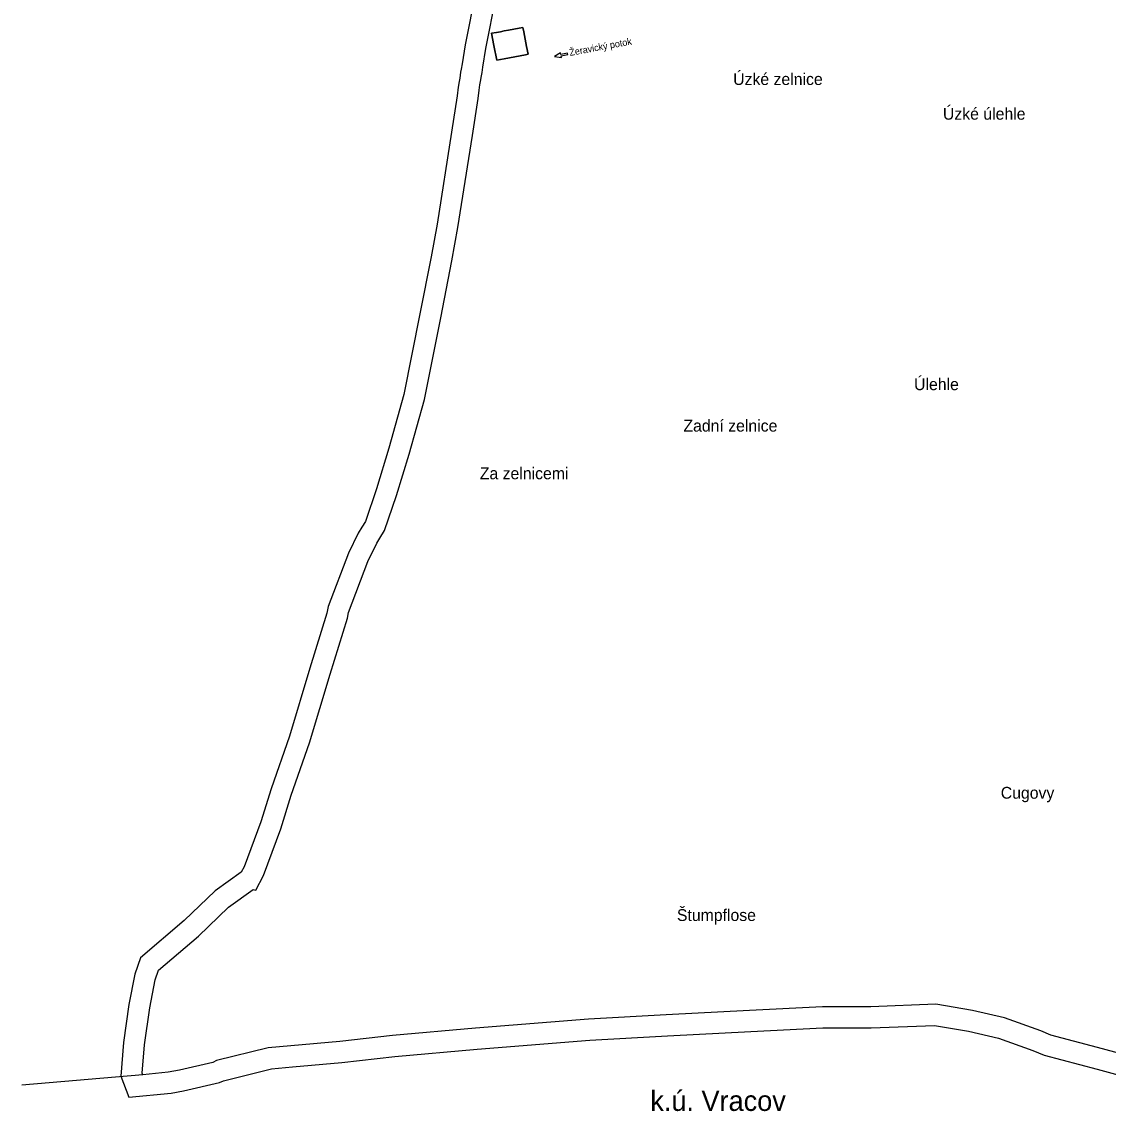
# Model space of a CAD drawing. Extents: x -555651 to -552898, y -1186794 to -1182535.
# Drawn here: x -555651 to -554364, y -1186786 to -1185494 of the extents above; entities that cross this region are included whole.
import ezdxf

# ---------------------------------------------------------------- set-up
doc = ezdxf.new("R2010")
doc.units = 0
for name, color, linetype in [('Level 2', 7, 'Continuous'), ('Level 3', 7, 'Continuous'), ('Level 30', 7, 'Continuous'), ('Level 32', 7, 'Continuous'), ('Level 57', 7, 'Continuous'), ('stav_OT', 7, 'Continuous'), ('ZASTAVENE_UZEMI', 7, 'Continuous')]:
    doc.layers.add(name, color=color, linetype=linetype)

msp = doc.modelspace()

# ---------------------------------------------------------------- linework, layer by layer
at = {"layer": 'Level 3'}
for p, q in [((-555012.854, -1185533.261), (-555013.267, -1185531.301)), ((-555005.023, -1185531.583), (-555012.854, -1185533.261)), ((-555012.513, -1185534.823), (-555004.692, -1185533.148)), ((-555012.095, -1185536.779), (-555012.513, -1185534.823)), ((-555004.692, -1185533.148), (-555005.023, -1185531.583))]:
    msp.add_line(p, q, dxfattribs=at)
for points in [[(-555013.267, -1185531.301), (-555020.506, -1185535.717)], [(-555020.506, -1185535.717), (-555012.095, -1185536.779)]]:
    msp.add_lwpolyline(points, dxfattribs=at)
at = {"layer": 'Level 30'}
for points in [[(-555113.633, -1185457.754), (-555126.215, -1185521.754), (-555129.927, -1185544.271), (-555130.948, -1185550.461), (-555131.577, -1185554.296), (-555132.73, -1185561.261), (-555133.36, -1185565.133), (-555134.498, -1185572.017), (-555135.598, -1185582.129), (-555142.388, -1185625.178), (-555159.376, -1185734.191), (-555166.618, -1185773.168), (-555179.758, -1185840.365), (-555198.817, -1185936.293), (-555216.478, -1185999.714), (-555231.301, -1186048.099), (-555244.387, -1186086.552), (-555248.487, -1186093.194), (-555252.857, -1186100.283), (-555264.519, -1186124.09), (-555288.498, -1186187.536), (-555289.998, -1186195.183), (-555310.113, -1186260.408), (-555334.437, -1186341.098), (-555356.203, -1186403.269), (-555368.444, -1186442.679), (-555388.188, -1186495.914), (-555391.439, -1186502.2), (-555422.576, -1186524.215), (-555459.116, -1186559.456), (-555511.009, -1186603.724), (-555517.63, -1186623.28), (-555524.573, -1186659.039), (-555530.99, -1186704.258)], [(-555506.13, -1186707.01), (-555499.91, -1186663.18), (-555493.41, -1186629.7), (-555489.54, -1186618.27), (-555442.31, -1186577.98), (-555406.59, -1186543.53), (-555377.44, -1186522.92), (-555374.35, -1186523.58), (-555365.28, -1186506.04), (-555344.77, -1186450.74), (-555332.46, -1186411.11), (-555310.66, -1186348.84), (-555286.2, -1186267.7), (-555265.72, -1186201.29), (-555264.37, -1186194.41), (-555241.55, -1186134.03), (-555230.94, -1186112.37), (-555227.21, -1186106.32), (-555221.63, -1186097.28), (-555207.51, -1186055.79), (-555192.48, -1186006.73), (-555174.48, -1185942.09), (-555155.23, -1185845.2), (-555142.06, -1185777.85), (-555134.73, -1185738.4), (-555117.69, -1185629.05), (-555110.81, -1185585.43), (-555109.72, -1185575.41), (-555108.69, -1185569.18), (-555108.06, -1185565.31), (-555106.91, -1185558.36), (-555106.28, -1185554.52), (-555105.26, -1185548.34), (-555101.61, -1185526.2), (-555089.38, -1185463.99)], [(-554318.68, -1186725.91), (-554371.15, -1186711.4), (-554432.23, -1186695.45), (-554444.35, -1186690.16), (-554487.24, -1186674.75), (-554525.06, -1186666.06), (-554568.51, -1186658.81), (-554645.82, -1186661.76), (-554703.03, -1186661.84), (-554789.24, -1186666.07), (-554887.97, -1186671.38), (-554980.05, -1186676.42), (-555114.15, -1186687.17), (-555212.22, -1186695.72), (-555274.79, -1186703.08), (-555332.83, -1186708.02)], [(-555330.71, -1186732.93), (-555272.269, -1186727.956), (-555209.673, -1186720.593), (-555112.065, -1186712.083), (-554978.368, -1186701.365), (-554886.616, -1186696.343), (-554787.956, -1186691.037), (-554702.4, -1186686.839), (-554645.326, -1186686.759), (-554570.107, -1186683.889), (-554529.921, -1186690.595), (-554494.291, -1186698.781), (-554453.587, -1186713.406), (-554440.438, -1186719.145), (-554377.64, -1186735.543), (-554325.272, -1186750.025)], [(-555530.99, -1186704.258), (-555534.153, -1186743.958), (-555524.481, -1186769.03), (-555474.566, -1186763.987), (-555459.837, -1186761.473), (-555417.205, -1186751.437), (-555412.5, -1186749.325), (-555355.454, -1186735.293), (-555330.71, -1186732.93)], [(-555332.83, -1186708.02), (-555359.65, -1186710.58), (-555420.67, -1186725.59), (-555425.26, -1186727.65), (-555464.81, -1186736.96), (-555477.93, -1186739.2), (-555508.02, -1186742.24), (-555508.78, -1186740.27), (-555506.13, -1186707.01)]]:
    msp.add_lwpolyline(points, dxfattribs=at)
at = {"layer": 'Level 32'}
msp.add_lwpolyline([(-555092.18, -1185522.55), (-555094.96, -1185508.08), (-555089.21, -1185507), (-555084.52, -1185506.13), (-555079.88, -1185505.26), (-555074.79, -1185504.31), (-555062.21, -1185501.96), (-555057.82, -1185501.14), (-555056.79, -1185506.46), (-555053.44, -1185523.9), (-555051.7, -1185532.91), (-555054.94, -1185533.53), (-555067.4, -1185535.93), (-555079.9, -1185538.34), (-555088.82, -1185540.06), (-555092.18, -1185522.55)], dxfattribs=at)
at = {"layer": 'Level 57'}
for points in [[(-555067.4, -1185535.93), (-555054.94, -1185533.53), (-555051.7, -1185532.91), (-555053.44, -1185523.9), (-555056.79, -1185506.46), (-555057.82, -1185501.14), (-555062.21, -1185501.96), (-555074.79, -1185504.31), (-555079.88, -1185505.26), (-555084.52, -1185506.13), (-555089.21, -1185507), (-555094.96, -1185508.08), (-555092.18, -1185522.55)], [(-555092.18, -1185522.55), (-555088.82, -1185540.06), (-555079.9, -1185538.34), (-555067.4, -1185535.93)]]:
    msp.add_lwpolyline(points, dxfattribs=at)
at = {"layer": 'stav_OT'}
for points in [[(-555506.13, -1186707.01), (-555499.91, -1186663.18), (-555493.41, -1186629.7), (-555489.54, -1186618.27), (-555442.31, -1186577.98), (-555406.59, -1186543.53), (-555377.44, -1186522.92), (-555374.35, -1186523.58), (-555365.28, -1186506.04), (-555344.77, -1186450.74), (-555332.46, -1186411.11), (-555310.66, -1186348.84), (-555286.2, -1186267.7), (-555265.72, -1186201.29), (-555264.37, -1186194.41), (-555241.55, -1186134.03), (-555230.94, -1186112.37), (-555227.21, -1186106.32), (-555221.63, -1186097.28), (-555207.51, -1186055.79), (-555192.48, -1186006.73), (-555174.48, -1185942.09), (-555155.23, -1185845.2), (-555142.06, -1185777.85), (-555134.73, -1185738.4), (-555117.69, -1185629.05), (-555110.81, -1185585.43), (-555109.72, -1185575.41), (-555108.69, -1185569.18), (-555108.06, -1185565.31), (-555106.91, -1185558.36), (-555106.28, -1185554.52), (-555105.26, -1185548.34), (-555101.61, -1185526.2), (-555089.38, -1185463.99)], [(-554318.68, -1186725.91), (-554371.15, -1186711.4), (-554432.23, -1186695.45), (-554444.35, -1186690.16), (-554487.24, -1186674.75), (-554525.06, -1186666.06), (-554568.51, -1186658.81), (-554645.82, -1186661.76), (-554703.03, -1186661.84), (-554789.24, -1186666.07), (-554887.97, -1186671.38), (-554980.05, -1186676.42), (-555114.15, -1186687.17), (-555212.22, -1186695.72), (-555274.79, -1186703.08), (-555332.83, -1186708.02)], [(-555332.83, -1186708.02), (-555359.65, -1186710.58), (-555420.67, -1186725.59), (-555425.26, -1186727.65), (-555464.81, -1186736.96), (-555477.93, -1186739.2), (-555508.02, -1186742.24), (-555508.78, -1186740.27), (-555506.13, -1186707.01)], [(-555508.02, -1186742.24), (-555651.457, -1186754.806)]]:
    msp.add_lwpolyline(points, dxfattribs=at)

# ---------------------------------------------------------------- texts
at = {"layer": 'Level 2'}
for s, p in [('Úzké zelnice', (-554808.775, -1185569.331)), ('Úzké úlehle', (-554560.255, -1185610.441)), ('Úlehle', (-554594.428, -1185930.971)), ('Zadní zelnice', (-554867.705, -1185980.101)), ('Za zelnicemi', (-555108.914, -1186036.566)), ('Cugovy', (-554491.756, -1186415.147)), ('Štumpflose', (-554875.401, -1186560.076))]:
    msp.add_text(s, height=14, dxfattribs=at).set_placement(p)
at = {"layer": 'Level 3'}
msp.add_text('Žeravický potok', height=8, rotation=10.468278, dxfattribs=at).set_placement((-555002.042, -1185534.921))
at = {"layer": 'ZASTAVENE_UZEMI'}
msp.add_text('k.ú. Vracov', height=24, dxfattribs=at).set_placement((-554906.909, -1186785.178))

doc.saveas('drawing.dxf')
